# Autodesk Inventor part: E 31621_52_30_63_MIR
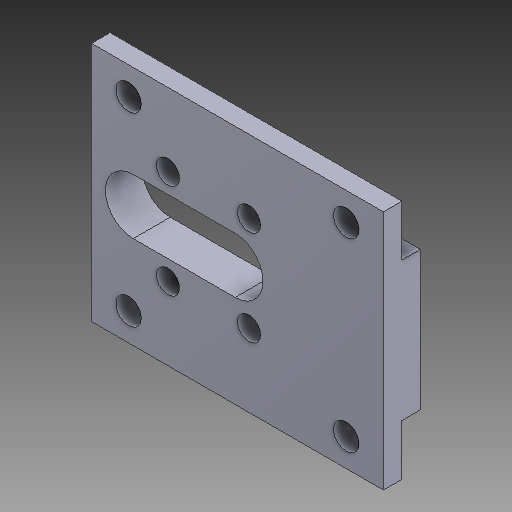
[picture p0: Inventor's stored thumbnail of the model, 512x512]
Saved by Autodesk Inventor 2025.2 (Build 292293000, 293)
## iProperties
Created: 2025-03
Part Number: E 31621_52_30_63_MIR
Material: Všeobecné
Document SubType Name: Modeling
Designer: Patrik
Mass: 16.5973 g
Surface Area: 85.6245 cm^2
Volume: 16.5973 cm^3
Density: 1 g/cm^3
Appearance: Výchozí
Author: Patrik
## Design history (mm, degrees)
derived "E 31621_52_30_63.ipt"
feature "Těleso1::E 31621_52_30_63.ipt" dims "d0" = 10
tag "Prvek štítků1"
node "Těleso1"
